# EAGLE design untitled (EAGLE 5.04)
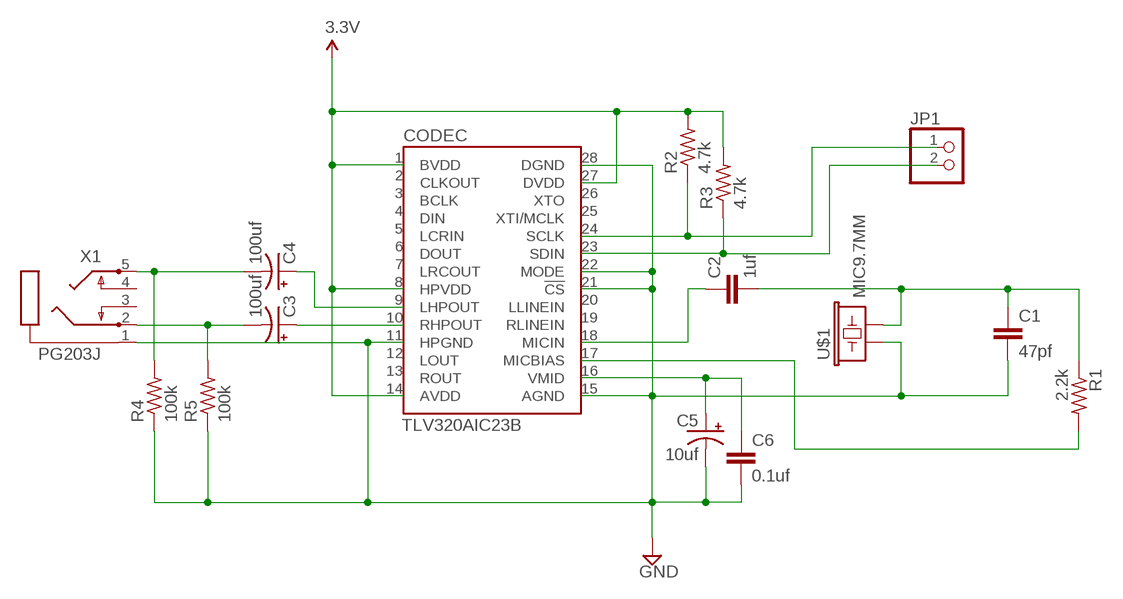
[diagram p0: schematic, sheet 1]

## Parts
C1  47pf  C-EU050-024X044  [C050-024X044]
C2  1uf  C-EU050-024X044  [C050-024X044]
C3  100uf  CPOL-USE2.5-7  [E2,5-7]
C4  100uf  CPOL-USE2.5-7  [E2,5-7]
C5  10uf  CPOL-USE2.5-7  [E2,5-7]
C6  0.1uf  C-EU050-024X044  [C050-024X044]
CODEC  TLV320AIC23B  [TSSOP28]
JP1  PINHD-1X2  [1X02]
R1  2.2k  R-US_0613/5V  [P0613V]
R2  4.7k  R-US_0613/5V  [P0613V]
R3  4.7k  R-US_0613/5V  [P0613V]
R4  100k  R-US_0613/5V  [P0613V]
R5  100k  R-US_0613/5V  [P0613V]
U$1  MIC9.7MM  [MIC-9.7MM]
X1  PG203J  [PG203J]

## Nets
3.3V: CODEC.1(BVDD) CODEC.8(HPVDD) CODEC.14(AVDD) CODEC.27(DVDD) R2.2 R3.2
GND: C1.2 C5.- C6.2 CODEC.11(HPGND) CODEC.15(AGND) CODEC.21(!CS) CODEC.22(MODE) CODEC.28(DGND) R4.1 R5.1 U$1.1 X1.1
N$1: C1.1 C2.2 R1.1 U$1.2
N$2: CODEC.17(MICBIAS) R1.2
N$3: C3.- R5.2 X1.2
N$4: C2.1 CODEC.18(MICIN)
N$5: CODEC.24(SCLK) JP1.1 R2.1
N$6: CODEC.23(SDIN) JP1.2 R3.1
N$7: C4.- R4.2 X1.5
N$8: C3.+ CODEC.10(RHPOUT)
N$9: C5.+ C6.1 CODEC.16(VMID)
N$11: C4.+ CODEC.9(LHPOUT)
Unconnected: CODEC.2(CLKOUT) CODEC.3(BCLK) CODEC.4(DIN) CODEC.5(LCRIN) CODEC.6(DOUT) CODEC.7(LRCOUT) CODEC.12(LOUT) CODEC.13(ROUT) CODEC.19(RLINEIN) CODEC.20(LLINEIN) CODEC.25(XTI/MCLK) CODEC.26(XTO) X1.3 X1.4

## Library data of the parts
C1 C2 C6 = rcl:C-EU: CAPACITOR, European symbol
C3-C5 = rcl:CPOL-US: POLARIZED CAPACITOR, American symbol
CODEC = trl:TLV320AIC23B
JP1 = pinhead:PINHD-1X2: PIN HEADER
R1-R5 = rcl:R-US_: RESISTOR, American symbol
U$1 = SparkFun:MIC: Microphone
X1 = con-hirschmann:PG203J: MIC/HEADPHONE JACK KS-S stereo microphone/headphone jack PG203JN (Schukat)

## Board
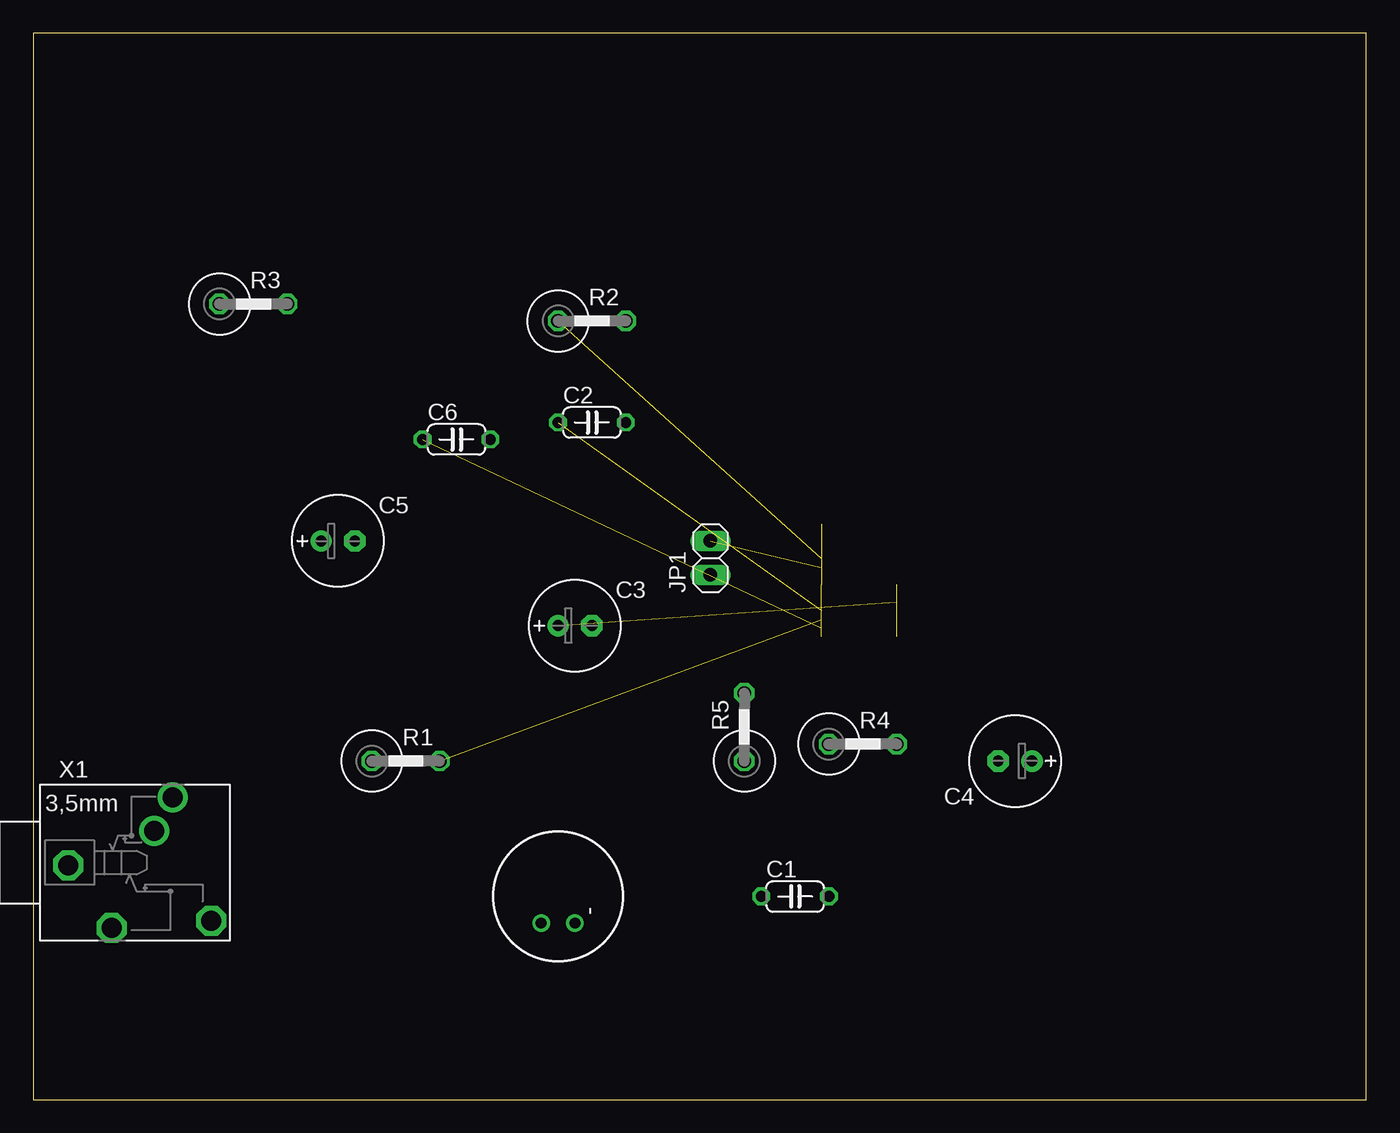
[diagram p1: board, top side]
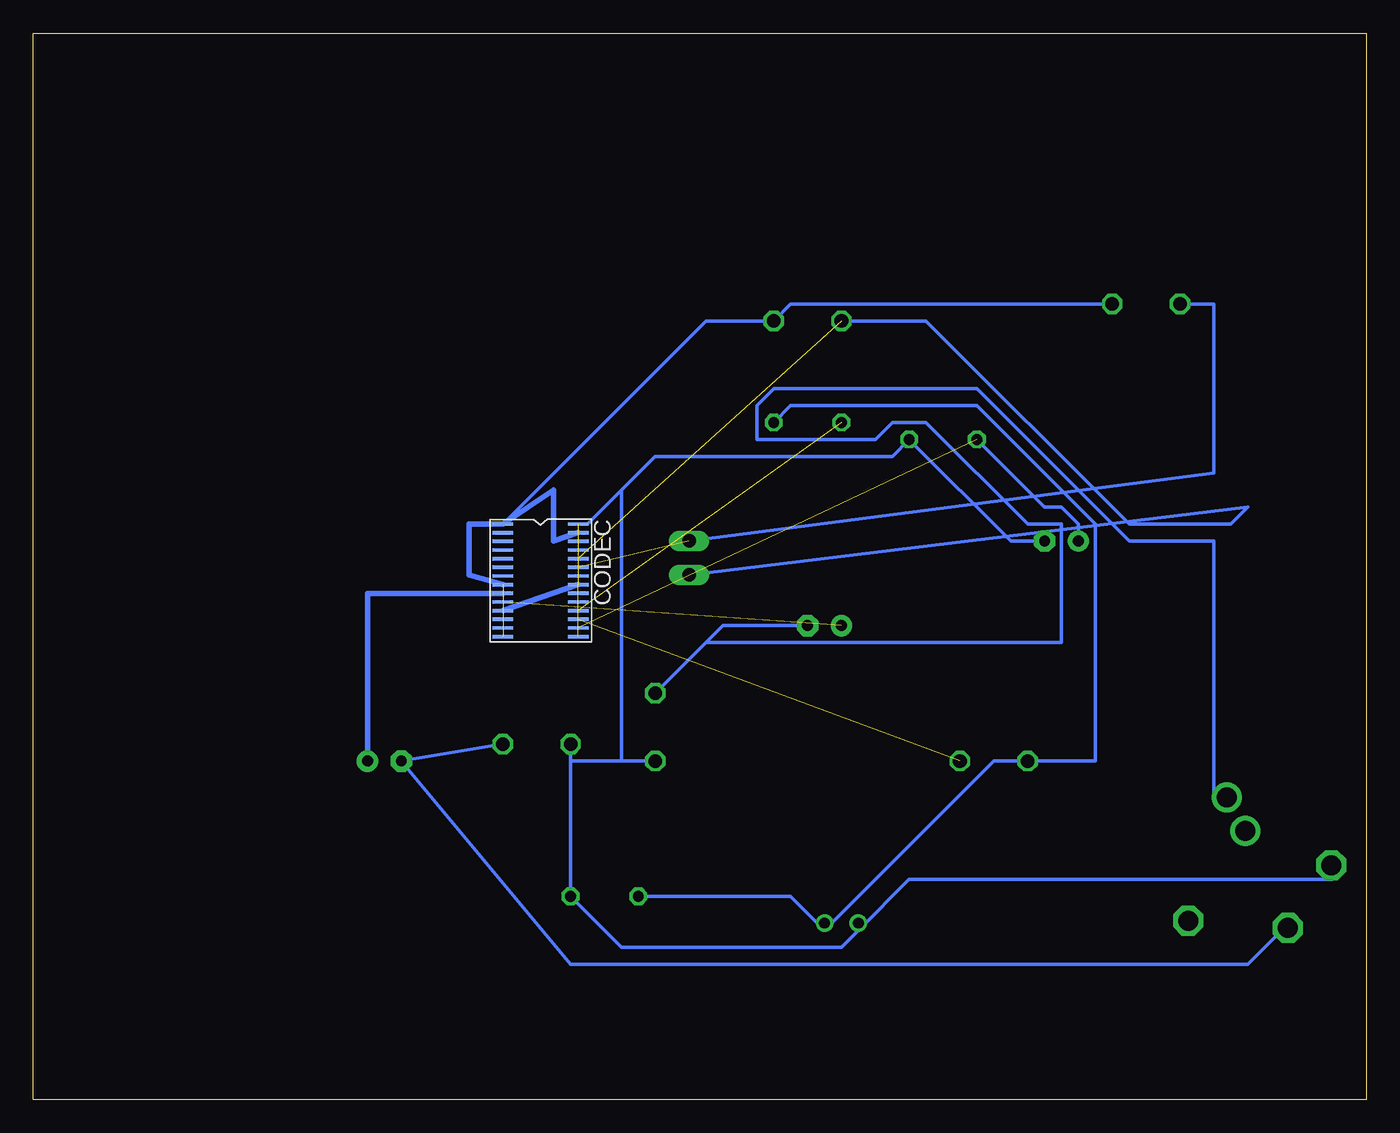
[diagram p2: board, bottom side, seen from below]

Size 100 x 80 mm. Coordinates in mm from the lower left corner, seen from the top.
Outline: 0,0 100,0 100,80 0,80 0,0
Copper layers (1*16): Top 0.035mm / dielectric 1.5mm / Bottom 0.035mm
Design rules "default": minimum track width 10mil, minimum drill 24mil, track to track 8mil, track to pad 8mil, pad to pad 8mil, via to via 8mil, smd to smd 8mil, copper to edge 40mil, drill to drill 8mil, minimum pad ring 10mil, minimum via ring 8mil, stop-mask expansion 4mil, vias tented up to drill 0mil, thermal gap 10mil

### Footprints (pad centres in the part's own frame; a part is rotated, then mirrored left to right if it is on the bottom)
C050-024X044 = drill 0.813 octagon: 1 -2.54,0; 2 2.54,0
E2,5-7 = drill 0.813 pad 1.6 round: + -1.27,0 | drill 0.813 pad 1.6 octagon: - 1.27,0
TSSOP28 = smd 0.25 x 1.55: 1 -3.81,-2.54; 2 -3.16,-2.54; 3 -2.51,-2.54; 4 -1.86,-2.54; 5 -1.21,-2.54; 6 -0.56,-2.54; 7 0.09,-2.54; 8 0.74,-2.54; 9 1.39,-2.54; 10 2.04,-2.54; 11 2.69,-2.54; 12 3.34,-2.54; 13 3.99,-2.54; 14 4.64,-2.54; 15 4.64,3.11; 16 3.99,3.11; 17 3.34,3.11; 18 2.69,3.11; 19 2.04,3.11; 20 1.39,3.11; 21 0.74,3.11; 22 0.09,3.11; 23 -0.56,3.11; 24 -1.21,3.11; 25 -1.86,3.11; 26 -2.51,3.11; 27 -3.16,3.11; 28 -3.81,3.11
1X02 = drill 1.016 long: 1 -1.27,0; 2 1.27,0
P0613V = drill 1.016 octagon: 1 -2.54,0; 2 2.54,0
MIC-9.7MM = drill 0.8 round: 1 -2,1.27; 2 -2,-1.27
PG203J = drill 1.499 octagon: 1 -5.004,-0.203; 4 5.74,-4.369; 5 -1.753,-4.902 | drill 1.499 round: 2 2.845,4.902; 3 1.448,2.388

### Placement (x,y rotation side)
C1  57.15,15.24 0 top
C2  41.91,50.8 0 top
C3  40.64,35.56 0 top
C4  73.66,25.4 180 top
C5  22.86,41.91 0 top
C6  31.75,49.53 0 top
CODEC  62.23,39.37 270 bottom
JP1  50.8,40.64 90 top
R1  27.94,25.4 0 top
R2  41.91,58.42 0 top
R3  16.51,59.69 0 top
R4  62.23,26.67 0 top
R5  53.34,27.94 90 top
U$1  39.37,15.24 90 top
X1  7.62,17.78 0 top

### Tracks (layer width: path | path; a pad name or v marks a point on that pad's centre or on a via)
3.3V  (1 unrouted)
  Bottom 0.254: CODEC.1 49.53,58.42 R2.2 43.18,59.69 R3.2
  Bottom 0.406: CODEC.8 67.31,39.37 67.31,43.18 CODEC.1 60.96,45.72 60.96,41.91 CODEC.27
GND  (3 unrouted)
  Bottom 0.254: 38.1,12.7 34.29,16.51 2.54,16.51 X1.1 | 38.1,12.7 U$1.1 38.1,12.7 | 59.69,25.4 R4.1 | 59.69,25.4 C1.2 55.88,11.43 39.37,11.43 38.1,12.7 | 59.69,25.4 55.88,25.4 | 55.88,25.4 R5.1 | 55.88,45.72 53.34,48.26 35.56,48.26 C6.2 26.67,41.91 C5.- | 55.88,45.72 58.42,43.18 CODEC.28 | 55.88,25.4 55.88,45.72
  Bottom 0.406: CODEC.21 CODEC.11
N$1
  Bottom 0.254: 40.64,12.7 43.18,15.24 C1.1 | 40.64,12.7 U$1.2 40.64,12.7 | C2.2 43.18,52.07 29.21,52.07 20.32,43.18 20.32,25.4 R1.1 27.94,25.4 40.64,12.7
N$2  (1 unrouted)
N$3
  Bottom 0.254: 49.53,34.29 48.26,35.56 C3.- | 49.53,34.29 R5.2 | 49.53,34.29 22.86,34.29 22.86,43.18 25.4,43.18 33.02,50.8 35.56,50.8 36.83,49.53 45.72,49.53 45.72,52.07 44.45,53.34 29.21,53.34 17.78,41.91 11.43,41.91 11.43,22.86 X1.2
N$4  (1 unrouted)
N$5  (1 unrouted)
  Bottom 0.254: R2.1 33.02,58.42 17.78,43.18 10.16,43.18 8.89,44.45 JP1.1
N$6  (1 unrouted)
  Bottom 0.254: R3.1 11.43,59.69 11.43,46.99 JP1.2
N$7
  Bottom 0.254: R4.2 C4.- 59.69,10.16 8.89,10.16 6.35,12.7 X1.5
N$8  (1 unrouted)
N$9  (1 unrouted)
  Bottom 0.254: C6.1 24.13,44.45 22.86,44.45 21.59,43.18 C5.+
N$11
  Bottom 0.406: CODEC.9 74.93,37.98 C4.+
